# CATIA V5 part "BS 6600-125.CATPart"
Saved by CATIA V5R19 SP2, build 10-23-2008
Part number: BS 6600-125
Bounding box of the stored display mesh (mm): x -59.975 to 59.975, y -59.975 to 59.975, z 0 to 325
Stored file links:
  C:\Users\Bora\Desktop\3D Katı model\BS serisi\BS 6600\BS 6600-125.CATPart
  C:\Program Files\Dassault Systemes\B19\intel_a\reffiles\standard\MetricThickPitch.txt
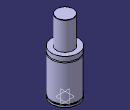
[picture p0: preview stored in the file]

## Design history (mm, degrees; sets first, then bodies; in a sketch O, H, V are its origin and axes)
Body1 (main body)
  Sketch1 on yz-plane, origin (0, 0, 0), H (0, 1, 0), V (0, 0, 1)
    point P1 (60, 179)
    point P2 (60, 174)
    point P3 (60, 179)
    point P7 (37.5, 324)
    point P9 (37.5, 324)
    point P14 (60, 174)
    arc A1 centre (60, 176.5) radius 2.5 from (60, 179) to (60, 174) ccw
    line L1 (60, 179) -> (60, 199)
    line L2 (60, 0) -> (60, 8)
    arc A2 centre (36.5, 324) radius 1 from (37.5, 324) to (36.5, 325) ccw
    line L3 (37.5, 324) -> (37.5, 199)
    line L4 (56, 13) -> (56, 8)
    line L5 (60, 13) -> (60, 174)
    line L6 (36.5, 325) -> (0, 325)
    point P15 (0, 325)
    line L7 (37.5, 199) -> (60, 199)
    line L8 (0, 0) -> (60, 0)
    line L9 (56, 13) -> (60, 13)
    line L10 (56, 8) -> (60, 8)
    coincidence: P15 V, P1 P3, P2 P14, P7 P9
    tangency: L6 A2
    horizontal: L7 H, L8 H, L9 H, L10 H
  Shaft1: profile Sketch1, axis Sketch1.V, angle 360
  Sketch2 on face of Shaft1 from Sketch1.L8, origin (0, 0, 0), H (1, 0, 0), V (0, -1, 0)
    point P1 (40, 0)
    distance P1 V = 40
  Hole1: placed by Sketch2, at (40, 0, 0) direction (0, 0, 1), diameter 8.376, depth 8, threaded "M10", thread diameter 10, thread depth 8, pitch 1.5
  CircPattern1: of Hole1, instances 4, angular step 90, axis from xy-plane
